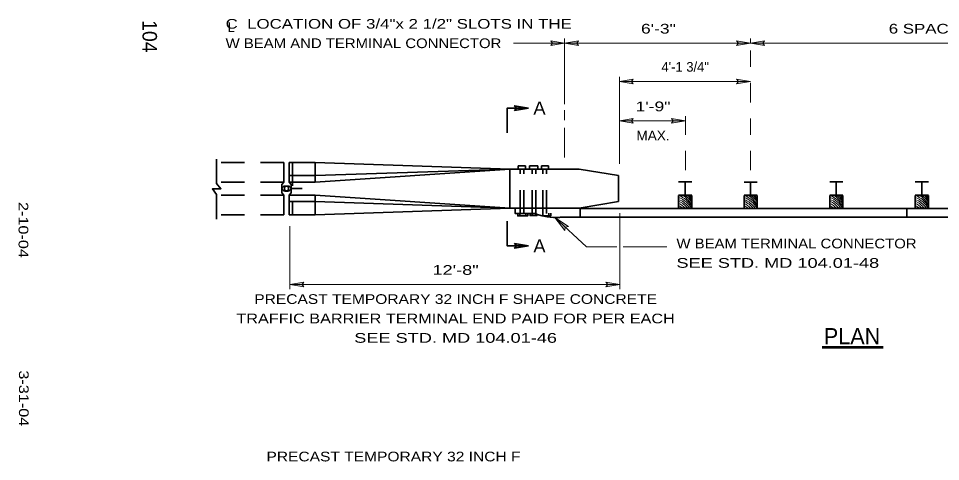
# Model space of a CAD drawing. Extents: x 49.7 to 60, y 209.2 to 216.1.
# Drawn here: x 50.38 to 56.09, y 213.39 to 216.13 of the extents above; entities that cross this region are included whole.
import ezdxf
from ezdxf.enums import TextEntityAlignment as Align

# ---------------------------------------------------------------- set-up
doc = ezdxf.new("R2010")
doc.units = 0
doc.header["$LTSCALE"] = 0.024
doc.linetypes.add('DOT_DASHED', pattern=[7.7, 5, -1.2, 0.3, -1.2])
doc.linetypes.add('LONG_DASHED', pattern=[7.5, 6, -1.5])
for name, color, linetype, lineweight in [('1', 7, 'Continuous', 35), ('10', 7, 'Continuous', 13), ('12', 7, 'Continuous', 53), ('13', 7, 'Continuous', 53), ('6', 7, 'Continuous', 13)]:
    doc.layers.add(name, color=color, linetype=linetype, lineweight=lineweight)

msp = doc.modelspace()

# ---------------------------------------------------------------- hatches: boundary and pattern name
at = {"layer": '10'}
for points in [[(53.75833, 215.97608), (53.67192, 215.9905), (53.68267, 215.97608), (53.67192, 215.96175)], [(53.75833, 215.97608), (53.84475, 215.9905), (53.83392, 215.97608), (53.84475, 215.96175)], [(54.82308, 215.96175), (54.9095, 215.97608), (54.82308, 215.9905), (54.83383, 215.97608)], [(54.99592, 215.9905), (54.9095, 215.97608), (54.99592, 215.96175), (54.98508, 215.97608)], [(54.17275, 215.74017), (54.18358, 215.75458), (54.09717, 215.74017), (54.18358, 215.72575)], [(54.82308, 215.72575), (54.9095, 215.74017), (54.82308, 215.75458), (54.83383, 215.74017)], [(53.53517, 215.57558), (53.44875, 215.56117), (53.45958, 215.57558), (53.44875, 215.59)], [(54.17275, 215.49558), (54.18358, 215.50992), (54.09717, 215.49558), (54.18358, 215.48117)], [(54.50567, 215.49558), (54.41925, 215.48117), (54.43008, 215.49558), (54.41925, 215.50992)], [(53.69683, 214.899), (53.75975, 214.8185), (53.76183, 214.83942), (53.7825, 214.84325)], [(53.53517, 214.72308), (53.44875, 214.7375), (53.45958, 214.72308), (53.44875, 214.70875)], [(52.14375, 214.46992), (52.05733, 214.48433), (52.14375, 214.49875), (52.133, 214.48433)], [(54.01417, 214.49875), (54.10058, 214.48433), (54.01417, 214.46992), (54.025, 214.48433)]]:
    msp.add_hatch(color=256, dxfattribs=at).paths.add_polyline_path(points)

# ---------------------------------------------------------------- linework, layer by layer
at = {"layer": '1', "linetype": 'LONG_DASHED'}
for p, q in [((52.01942, 215.2385), (51.60592, 215.2385)), ((52.01942, 215.11767), (52.01942, 215.2385)), ((52.0735, 215.23808), (52.0735, 214.91742)), ((53.48367, 214.92417), (53.48367, 215.19825)), ((53.50592, 214.92417), (53.50592, 215.19825)), ((53.55775, 214.92417), (53.55775, 215.19975)), ((53.58, 214.92408), (53.58, 215.19975)), ((53.62392, 214.92408), (53.62392, 215.19917)), ((53.64608, 214.92408), (53.64608, 215.19917)), ((52.00675, 215.07725), (52.00675, 215.10283)), ((52.00675, 215.05092), (52.00675, 215.07725)), ((52.00675, 215.05092), (52.01942, 215.03708)), ((52.06567, 215.07767), (52.13325, 215.07767)), ((52.01942, 214.91617), (51.60592, 214.91617))]:
    msp.add_line(p, q, dxfattribs=at)
at = {"layer": '1'}
for p, q in [((52.053, 215.11767), (52.053, 215.2385)), ((52.21425, 215.11767), (52.21425, 215.2385)), ((52.21425, 215.11767), (53.41908, 215.19825)), ((53.47125, 215.19808), (53.47125, 215.2185)), ((53.47125, 215.2185), (53.516, 215.2185)), ((53.516, 215.19808), (53.516, 215.2185)), ((53.54158, 215.19808), (53.54158, 215.2185)), ((53.54158, 215.2185), (53.59167, 215.2185)), ((53.59167, 215.19808), (53.59167, 215.2185)), ((53.614, 215.19808), (53.614, 215.2185)), ((53.614, 215.2185), (53.65883, 215.2185)), ((53.65883, 215.19808), (53.65883, 215.2185)), ((53.84892, 215.19825), (54.09075, 215.15783)), ((54.09075, 214.99675), (54.09075, 215.15783)), ((52.06567, 215.07725), (52.06567, 215.10283)), ((54.46367, 215.11825), (54.54508, 215.11825)), ((54.50433, 215.03692), (54.50433, 215.11825)), ((54.86892, 215.11808), (54.95033, 215.11808)), ((54.90958, 215.03675), (54.90958, 215.11808)), ((55.39983, 215.11825), (55.48125, 215.11825)), ((55.4405, 215.03692), (55.4405, 215.11825)), ((55.929, 215.11825), (56.0105, 215.11825)), ((55.96967, 215.03692), (55.96967, 215.11825)), ((52.06567, 215.05092), (52.053, 215.03708)), ((52.06567, 215.05092), (52.06567, 215.07725)), ((52.21425, 215.03708), (53.41908, 214.9565)), ((52.21425, 214.91617), (52.21425, 215.03275)), ((54.46367, 215.03692), (54.545, 215.03692)), ((54.46367, 215.03558), (54.46367, 214.9555)), ((54.46367, 215.03558), (54.545, 215.03558)), ((54.545, 215.03558), (54.545, 214.9555)), ((54.86892, 215.03675), (54.95025, 215.03675)), ((54.86892, 215.03542), (54.86892, 214.95533)), ((54.86892, 215.03542), (54.95025, 215.03542)), ((54.95025, 215.03542), (54.95025, 214.95533)), ((55.39983, 215.03692), (55.48117, 215.03692)), ((55.39983, 215.03558), (55.39983, 214.9555)), ((55.39983, 215.03558), (55.48117, 215.03558)), ((55.48117, 215.03558), (55.48117, 214.9555)), ((55.929, 215.03692), (56.01033, 215.03692)), ((55.929, 215.03558), (55.929, 214.9555)), ((55.929, 215.03558), (56.01033, 215.03558)), ((56.01033, 215.03558), (56.01033, 214.9555)), ((52.053, 214.99675), (52.21425, 214.99675)), ((52.21425, 214.99675), (53.41908, 214.9565)), ((53.84892, 214.9565), (54.09075, 214.99675)), ((53.84892, 214.9565), (53.41908, 214.9565)), ((53.48083, 214.90892), (53.48083, 214.92417)), ((53.518, 214.90892), (53.518, 214.92417)), ((53.55775, 214.9105), (53.55775, 214.92417)), ((53.58867, 214.9105), (53.58867, 214.91783)), ((53.62392, 214.90983), (53.62392, 214.92508)), ((53.66108, 214.90983), (53.66108, 214.92508)), ((53.85392, 214.954), (59.47, 214.954)), ((53.85392, 214.89975), (53.85392, 214.954)), ((54.46367, 214.9555), (54.545, 214.9555)), ((54.86892, 214.95533), (54.95025, 214.95533)), ((55.39983, 214.9555), (55.48117, 214.9555)), ((55.87783, 214.90025), (55.87783, 214.95458)), ((55.929, 214.9555), (56.01033, 214.9555)), ((59.47, 214.89975), (53.72958, 214.89975))]:
    msp.add_line(p, q, dxfattribs=at)
for points in [[(52.053, 215.2385), (52.21425, 215.2385), (53.41908, 215.19825)], [(52.053, 215.15783), (52.21425, 215.15783), (53.41908, 215.19825)], [(53.84892, 215.19825), (53.41908, 215.19825), (53.41908, 214.9565)], [(52.06567, 215.10283), (52.053, 215.11767), (52.21425, 215.11767)], [(52.053, 214.91617), (52.053, 215.03708), (52.21425, 215.03708)], [(52.053, 214.91617), (52.21425, 214.91617), (53.41908, 214.9565)], [(53.572, 214.92417), (53.45125, 214.92417), (53.45125, 214.9565)], [(53.46783, 214.92417), (53.46783, 214.90892), (53.52975, 214.90892), (53.52975, 214.92417)], [(53.54475, 214.92417), (53.54475, 214.9105), (53.58867, 214.9105)], [(53.61725, 214.90983), (53.67283, 214.90983), (53.67283, 214.92508)]]:
    msp.add_lwpolyline(points, dxfattribs=at)
at = {"layer": '1', "linetype": 'LONG_DASHED'}
for points in [[(52.00675, 215.10283), (52.01942, 215.11767), (51.60592, 215.11767)], [(52.01942, 214.91617), (52.01942, 215.03708), (51.60725, 215.03708)]]:
    msp.add_lwpolyline(points, dxfattribs=at)
at = {"layer": '1'}
for centre, radius, start, end in [((52.03027, 215.06763), 0.02558, 58.21372, 156.93818), ((52.03879, 215.07765), 0.01554, 131.05518, 228.94482), ((52.04205, 215.06763), 0.02558, 23.06182, 121.78628), ((52.03353, 215.07765), 0.01554, 311.05518, 48.94482), ((52.03027, 215.08767), 0.02558, 203.06182, 301.78628), ((52.04205, 215.08767), 0.02558, 238.21372, 336.93818), ((53.70524, 215.26372), 0.36484, 248.57561, 273.81771)]:
    msp.add_arc(centre, radius, start, end, dxfattribs=at)
at = {"layer": '10'}
for p, q in [((53.75833, 216.00492), (53.75833, 215.5985)), ((54.9095, 215.97608), (54.9095, 216.00492)), ((53.44225, 215.97608), (53.75833, 215.97608)), ((53.67192, 215.9905), (53.75833, 215.97608)), ((53.67192, 215.9905), (53.68267, 215.97608)), ((53.67192, 215.96175), (53.75833, 215.97608)), ((53.67192, 215.96175), (53.68267, 215.97608)), ((53.84475, 215.9905), (53.75833, 215.97608)), ((53.75833, 215.97608), (54.9095, 215.97608)), ((53.84475, 215.96175), (53.75833, 215.97608)), ((53.84475, 215.9905), (53.83392, 215.97608)), ((53.84475, 215.96175), (53.83392, 215.97608)), ((54.82308, 215.9905), (54.9095, 215.97608)), ((54.82308, 215.9905), (54.83383, 215.97608)), ((54.82308, 215.96175), (54.9095, 215.97608)), ((54.82308, 215.96175), (54.83383, 215.97608)), ((54.99592, 215.9905), (54.9095, 215.97608)), ((58.08642, 215.97608), (54.9095, 215.97608)), ((54.99592, 215.96175), (54.9095, 215.97608)), ((54.99592, 215.9905), (54.98508, 215.97608)), ((54.99592, 215.96175), (54.98508, 215.97608)), ((54.09717, 215.22983), (54.09717, 215.769)), ((54.18358, 215.75458), (54.09717, 215.74017)), ((54.09717, 215.74017), (54.9095, 215.74017)), ((54.18358, 215.72575), (54.09717, 215.74017)), ((54.18358, 215.75458), (54.17275, 215.74017)), ((54.18358, 215.72575), (54.17275, 215.74017)), ((54.82308, 215.75458), (54.9095, 215.74017)), ((54.82308, 215.75458), (54.83383, 215.74017)), ((54.82308, 215.72575), (54.9095, 215.74017)), ((54.82308, 215.72575), (54.83383, 215.74017)), ((53.75833, 215.50058), (53.75833, 215.56308)), ((54.18358, 215.50992), (54.09717, 215.49558)), ((54.09717, 215.49558), (54.50567, 215.49558)), ((54.18358, 215.48117), (54.09717, 215.49558)), ((54.18358, 215.50992), (54.17275, 215.49558)), ((54.18358, 215.48117), (54.17275, 215.49558)), ((54.41925, 215.50992), (54.50567, 215.49558)), ((54.41925, 215.50992), (54.43008, 215.49558)), ((54.41925, 215.48117), (54.50567, 215.49558)), ((54.41925, 215.48117), (54.43008, 215.49558)), ((54.50567, 215.49558), (54.50567, 215.52433)), ((53.75833, 215.27025), (53.75833, 215.45367)), ((54.10058, 214.92475), (54.10058, 214.4555)), ((53.75975, 214.8185), (53.69683, 214.899)), ((53.7825, 214.84325), (53.69683, 214.899)), ((53.69683, 214.899), (53.89383, 214.71833)), ((52.05733, 214.84417), (52.05733, 214.4555)), ((53.75975, 214.8185), (53.76183, 214.83942)), ((53.7825, 214.84325), (53.76183, 214.83942)), ((53.89383, 214.71833), (54.08142, 214.71833)), ((54.39133, 214.71833), (54.11983, 214.71833)), ((52.14375, 214.49875), (52.05733, 214.48433)), ((52.05733, 214.48433), (54.10058, 214.48433)), ((52.14375, 214.46992), (52.05733, 214.48433)), ((52.14375, 214.49875), (52.133, 214.48433)), ((52.14375, 214.46992), (52.133, 214.48433)), ((54.01417, 214.49875), (54.10058, 214.48433)), ((54.01417, 214.49875), (54.025, 214.48433)), ((54.01417, 214.46992), (54.10058, 214.48433)), ((54.01417, 214.46992), (54.025, 214.48433))]:
    msp.add_line(p, q, dxfattribs=at)
at = {"layer": '10', "linetype": 'DOT_DASHED'}
for p, q in [((54.9095, 215.19067), (54.9095, 216.00492)), ((54.50567, 215.19067), (54.50567, 215.51958))]:
    msp.add_line(p, q, dxfattribs=at)
at = {"layer": '10', "lineweight": 35}
for p, q in [((53.44875, 215.59), (53.53517, 215.57558)), ((53.44875, 215.59), (53.45958, 215.57558)), ((53.44875, 215.56117), (53.53517, 215.57558)), ((53.44875, 215.56117), (53.45958, 215.57558)), ((51.60317, 215.04233), (51.60317, 214.88875)), ((53.44875, 214.7375), (53.53517, 214.72308)), ((53.44875, 214.7375), (53.45958, 214.72308)), ((53.44875, 214.70875), (53.53517, 214.72308)), ((53.44875, 214.70875), (53.45958, 214.72308))]:
    msp.add_line(p, q, dxfattribs=at)
at = {"layer": '10'}
for points in [[(53.75833, 215.97608), (53.67192, 215.9905), (53.68267, 215.97608), (53.67192, 215.96175)], [(53.75833, 215.97608), (53.84475, 215.9905), (53.83392, 215.97608), (53.84475, 215.96175)], [(54.82308, 215.96175), (54.9095, 215.97608), (54.82308, 215.9905), (54.83383, 215.97608)], [(54.99592, 215.9905), (54.9095, 215.97608), (54.99592, 215.96175), (54.98508, 215.97608)], [(54.17275, 215.74017), (54.18358, 215.75458), (54.09717, 215.74017), (54.18358, 215.72575)], [(54.82308, 215.72575), (54.9095, 215.74017), (54.82308, 215.75458), (54.83383, 215.74017)], [(54.17275, 215.49558), (54.18358, 215.50992), (54.09717, 215.49558), (54.18358, 215.48117)], [(54.50567, 215.49558), (54.41925, 215.48117), (54.43008, 215.49558), (54.41925, 215.50992)], [(53.69683, 214.899), (53.75975, 214.8185), (53.76183, 214.83942), (53.7825, 214.84325)], [(52.14375, 214.46992), (52.05733, 214.48433), (52.14375, 214.49875), (52.133, 214.48433)], [(54.01417, 214.49875), (54.10058, 214.48433), (54.01417, 214.46992), (54.025, 214.48433)]]:
    msp.add_lwpolyline(points, close=True, dxfattribs=at)
at = {"layer": '10', "lineweight": 35}
for points in [[(53.40292, 215.42167), (53.40292, 215.57558), (53.53517, 215.57558)], [(51.60317, 215.26), (51.60317, 215.10942), (51.63042, 215.07633), (51.57717, 215.07517), (51.60317, 215.041)], [(53.40292, 214.877), (53.40292, 214.72308), (53.53517, 214.72308)]]:
    msp.add_lwpolyline(points, dxfattribs=at)
for points in [[(53.53517, 215.57558), (53.44875, 215.56117), (53.45958, 215.57558), (53.44875, 215.59)], [(53.53517, 214.72308), (53.44875, 214.7375), (53.45958, 214.72308), (53.44875, 214.70875)]]:
    msp.add_lwpolyline(points, close=True, dxfattribs=at)
at = {"layer": '12'}
msp.add_line((55.35208, 214.09617), (55.73008, 214.09617), dxfattribs=at)
at = {"layer": '6'}
for centre, radius, start, end in [((54.40861, 214.87558), 0.15754, 30.50061, 69.49881), ((54.38929, 214.86339), 0.18836, 34.17863, 66.11666), ((54.38537, 214.87918), 0.18798, 31.80949, 56.32878), ((54.3915, 214.8853), 0.18798, 35.19443, 53.09813), ((54.3873, 214.90169), 0.18798, 32.90846, 45.43912), ((54.3873, 214.91219), 0.18798, 32.90846, 41.04364), ((54.38268, 214.93151), 0.18798, 30.21852, 33.63016), ((54.81386, 214.87541), 0.15754, 30.50061, 69.49881), ((54.79454, 214.86323), 0.18836, 34.17863, 66.11666), ((54.79062, 214.87901), 0.18798, 31.80949, 56.32878), ((54.79675, 214.88513), 0.18798, 35.19443, 53.09813), ((54.79255, 214.90152), 0.18798, 32.90846, 45.43912), ((54.79255, 214.91202), 0.18798, 32.90846, 41.04364), ((54.78793, 214.93135), 0.18798, 30.21852, 33.63016), ((55.34478, 214.87558), 0.15754, 30.50061, 69.49881), ((55.32546, 214.86339), 0.18836, 34.17863, 66.11666), ((55.32154, 214.87918), 0.18798, 31.80949, 56.32878), ((55.32767, 214.8853), 0.18798, 35.19443, 53.09813), ((55.32347, 214.90169), 0.18798, 32.90846, 45.43912), ((55.32347, 214.91219), 0.18798, 32.90846, 41.04364), ((55.31885, 214.93151), 0.18798, 30.21852, 33.63016), ((55.87394, 214.87558), 0.15754, 30.50061, 69.49881), ((55.85463, 214.86339), 0.18836, 34.17863, 66.11666), ((55.85071, 214.87918), 0.18798, 31.80949, 56.32878), ((55.85683, 214.8853), 0.18798, 35.19443, 53.09813), ((55.85264, 214.90169), 0.18798, 32.90846, 45.43912), ((55.85264, 214.91219), 0.18798, 32.90846, 41.04364), ((55.84802, 214.93151), 0.18798, 30.21852, 33.63016), ((54.41727, 214.88195), 0.12585, 35.78195, 68.31044), ((54.42911, 214.89772), 0.09472, 37.61828, 68.52708), ((54.43555, 214.90237), 0.07566, 44.64315, 68.09106), ((54.40825, 214.86913), 0.15183, 34.69089, 68.54375), ((54.82252, 214.88178), 0.12585, 35.78195, 68.31044), ((54.83436, 214.89756), 0.09472, 37.61828, 68.52708), ((54.8408, 214.9022), 0.07566, 44.64315, 68.09106), ((54.8135, 214.86896), 0.15183, 34.69089, 68.54375), ((55.35344, 214.88195), 0.12585, 35.78195, 68.31044), ((55.36528, 214.89772), 0.09472, 37.61828, 68.52708), ((55.37172, 214.90237), 0.07566, 44.64315, 68.09106), ((55.34442, 214.86913), 0.15183, 34.69089, 68.54375), ((55.87358, 214.86913), 0.15183, 34.69089, 68.54375), ((55.88261, 214.88195), 0.12585, 35.78195, 68.31044), ((55.89445, 214.89772), 0.09472, 37.61828, 68.52708), ((55.90089, 214.90237), 0.07566, 44.64315, 68.09106), ((54.44093, 214.90978), 0.05615, 54.58973, 65.97576), ((54.84618, 214.90961), 0.05615, 54.58973, 65.97576), ((55.37709, 214.90978), 0.05615, 54.58973, 65.97576), ((55.90626, 214.90978), 0.05615, 54.58973, 65.97576)]:
    msp.add_arc(centre, radius, start, end, dxfattribs=at)

# ---------------------------------------------------------------- texts
at = {"layer": '12'}
for s, width, p in [('C  LOCATION OF 3/4"x 2 1/2" SLOTS IN THE', 1.3, (51.65917, 216.06608)), ('W BEAM AND TERMINAL CONNECTOR', 1.15, (51.65917, 215.946)), ('W BEAM TERMINAL CONNECTOR', 1.15, (54.45067, 214.70767)), ('SEE STD. MD 104.01-48', 1.4, (54.45067, 214.58767)), ('PRECAST TEMPORARY 32 INCH F', 1.2, (51.912, 213.39067))]:
    msp.add_text(s, height=0.06001, dxfattribs=dict(at, width=width)).set_placement(p)
msp.add_text('L', height=0.06001, dxfattribs=at).set_placement((51.67175, 216.04583))
for s, width, p in [('6\'-3"', 1.35, (54.33888, 216.036)), ('6 SPACES AT 3\'-1 1/2" = 18\'-9"', 1.3, (56.49912, 216.036)), ('1\'-9"', 1.35, (54.30554, 215.5555)), ('MAX.', 1.05, (54.30554, 215.37542)), ('12\'-8"', 1.4, (53.08312, 214.54425)), ('PRECAST TEMPORARY 32 INCH F SHAPE CONCRETE', 1.2, (53.08317, 214.36425)), ('TRAFFIC BARRIER TERMINAL END PAID FOR PER EACH', 1.25, (53.08312, 214.24417)), ('SEE STD. MD 104.01-46', 1.4, (53.08312, 214.12417))]:
    msp.add_text(s, height=0.06001, dxfattribs=dict(at, width=width)).set_placement(p, align=Align.CENTER)
for s, height, p in [('4\'-1 3/4"', 0.06001, (54.50487, 215.80008)), ('PLAN', 0.1, (55.53787, 214.11475))]:
    msp.add_text(s, height=height, dxfattribs=at).set_placement(p, align=Align.CENTER)
at = {"layer": '13'}
msp.add_text('104', height=0.09001, rotation=270, dxfattribs=at).set_placement((51.14425, 216.01871), align=Align.CENTER)
at = {"layer": '13', "width": 1.05}
for p in [(53.56508, 215.5355), (53.56508, 214.683)]:
    msp.add_text('A', height=0.08001, dxfattribs=at).set_placement(p)
at = {"layer": '13', "width": 1.25}
for s, p in [('2-10-04', (50.37717, 214.64892)), ('3-31-04', (50.3795, 213.60783))]:
    msp.add_text(s, height=0.06, rotation=270, dxfattribs=at).set_placement(p, align=Align.RIGHT)

doc.saveas('drawing.dxf')
